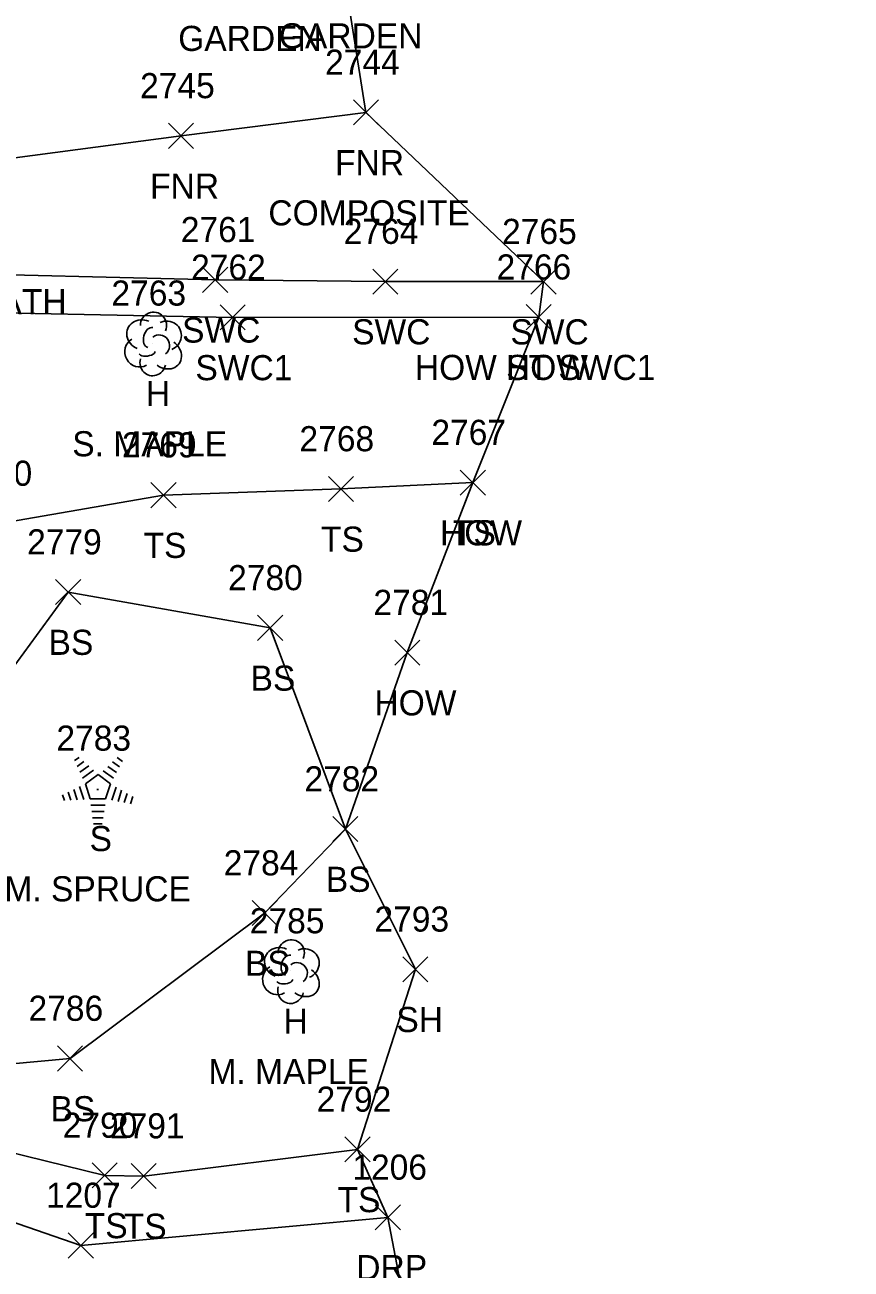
# Model space of a CAD drawing. Extents: x 1461855 to 1464118, y 556196 to 557441.
# Drawn here: x 1462432.1 to 1462498, y 556585 to 556684.1 of the extents above; entities that cross this region are included whole.
import ezdxf

# ---------------------------------------------------------------- set-up
doc = ezdxf.new("R2010")
doc.units = 0
for name, color, linetype in [('L_A', 7, 'Continuous'), ('L_C', 7, 'Continuous'), ('L_I', 7, 'Continuous'), ('L_TIC', 7, 'Continuous'), ('LBC', 7, 'Continuous'), ('LELB', 7, 'Continuous'), ('LFNC', 7, 'Continuous'), ('LSOGP', 7, 'Continuous'), ('LTC', 7, 'Continuous'), ('LTD', 7, 'Continuous'), ('R_A', 7, 'Continuous'), ('R_I', 7, 'Continuous'), ('R_TIC', 7, 'Continuous'), ('RDP', 7, 'Continuous'), ('RSW', 7, 'Continuous')]:
    doc.layers.add(name, color=color, linetype=linetype)

msp = doc.modelspace()

# ---------------------------------------------------------------- linework, layer by layer
at = {"layer": 'L_TIC'}
for points in [[(1462458.317, 556676.129), (1462460.317, 556678.129)], [(1462460.317, 556676.129), (1462458.317, 556678.129)], [(1462443.579, 556674.26), (1462445.579, 556676.26)], [(1462445.579, 556674.26), (1462443.579, 556676.26)], [(1462472.082, 556659.822), (1462474.082, 556661.822)], [(1462474.082, 556659.822), (1462472.082, 556661.822)], [(1462466.833, 556646.652), (1462468.833, 556648.652)], [(1462468.833, 556646.652), (1462466.833, 556648.652)], [(1462466.833, 556646.652), (1462468.833, 556648.652)], [(1462468.833, 556646.652), (1462466.833, 556648.652)], [(1462442.184, 556645.651), (1462444.184, 556647.651)], [(1462444.184, 556645.651), (1462442.184, 556647.651)], [(1462456.322, 556646.145), (1462458.322, 556648.145)], [(1462458.322, 556646.145), (1462456.322, 556648.145)], [(1462434.585, 556637.93), (1462436.585, 556639.93)], [(1462436.585, 556637.93), (1462434.585, 556639.93)], [(1462450.68, 556635.08), (1462452.68, 556637.08)], [(1462452.68, 556635.08), (1462450.68, 556637.08)], [(1462461.604, 556633.11), (1462463.604, 556635.11)], [(1462463.604, 556633.11), (1462461.604, 556635.11)], [(1462456.674, 556619.06), (1462458.674, 556621.06)], [(1462458.674, 556619.06), (1462456.674, 556621.06)], [(1462450.24, 556612.372), (1462452.24, 556614.372)], [(1462452.24, 556612.372), (1462450.24, 556614.372)], [(1462462.251, 556607.893), (1462464.251, 556609.893)], [(1462464.251, 556607.893), (1462462.251, 556609.893)], [(1462434.743, 556600.789), (1462436.743, 556602.789)], [(1462436.743, 556600.789), (1462434.743, 556602.789)], [(1462457.64, 556593.551), (1462459.64, 556595.551)], [(1462459.64, 556593.551), (1462457.64, 556595.551)], [(1462437.5, 556591.477), (1462439.5, 556593.477)], [(1462439.5, 556591.477), (1462437.5, 556593.477)], [(1462440.607, 556591.429), (1462442.607, 556593.429)], [(1462442.607, 556591.429), (1462440.607, 556593.429)]]:
    msp.add_lwpolyline(points, dxfattribs=at)
at = {"layer": 'LBC'}
msp.add_lwpolyline([(1462473.082, 556660.822), (1462467.833, 556647.652), (1462462.604, 556634.11)], dxfattribs=at)
at = {"layer": 'LELB'}
for points in [[(1462398.71, 556863.574), (1462402.391, 556852.24), (1462404.798, 556832.693), (1462410.819, 556809.539), (1462407.679, 556805.323), (1462406.455, 556784.092), (1462410.476, 556745.251), (1462412.025, 556715.66), (1462414.021, 556699.927), (1462415.956, 556675.834), (1462416.655, 556662.842), (1462419.224, 556640.169), (1462421.298, 556615.254), (1462423.719, 556596.606), (1462425.734, 556595.598), (1462438.5, 556592.477), (1462441.607, 556592.429), (1462458.64, 556594.551)], [(1462467.833, 556647.652), (1462457.322, 556647.145), (1462443.184, 556646.651), (1462430.121, 556644.395), (1462421.458, 556640.596)], [(1462423.571, 556615.497), (1462428.501, 556629.264), (1462435.585, 556638.93), (1462451.68, 556636.08), (1462457.674, 556620.06), (1462451.24, 556613.372), (1462435.743, 556601.789), (1462426.19, 556600.924)]]:
    msp.add_lwpolyline(points, dxfattribs=at)
at = {"layer": 'LFNC'}
msp.add_lwpolyline([(1462459.317, 556677.129), (1462444.579, 556675.26), (1462422.678, 556672.378), (1462423.303, 556665.036)], dxfattribs=at)
at = {"layer": 'LSOGP'}
msp.add_lwpolyline([(1462492.963, 556484.557), (1462497.969, 556513.067), (1462493.382, 556525.455), (1462494.578, 556544.983), (1462465.288, 556544.702), (1462464.985, 556558.784), (1462464.727, 556563.689), (1462463.774, 556573.431), (1462464.38, 556574.975), (1462463.349, 556577.214), (1462461.053, 556589.139), (1462458.64, 556594.551), (1462463.251, 556608.893), (1462457.674, 556620.06), (1462462.604, 556634.11), (1462467.833, 556647.652), (1462473.082, 556660.822), (1462473.463, 556663.653), (1462459.317, 556677.129), (1462457.706, 556687.223)], dxfattribs=at)
at = {"layer": 'LTC'}
for p, q in [((1462436.104, 556625.51), (1462436.458, 556625.767)), ((1462436.313, 556625.044), (1462436.842, 556625.429)), ((1462439.131, 556625.402), (1462439.68, 556625.003)), ((1462439.502, 556625.75), (1462439.921, 556625.446)), ((1462436.523, 556624.579), (1462437.227, 556625.09)), ((1462436.732, 556624.113), (1462437.611, 556624.751)), ((1462436.957, 556623.658), (1462437.969, 556624.392)), ((1462437.969, 556624.392), (1462438.966, 556623.667)), ((1462438.389, 556624.705), (1462439.198, 556624.117)), ((1462438.76, 556625.054), (1462439.439, 556624.56)), ((1462436.502, 556623.439), (1462436.833, 556622.42)), ((1462436.957, 556623.658), (1462437.344, 556622.465)), ((1462438.966, 556623.667), (1462438.574, 556622.465)), ((1462439.403, 556623.397), (1462439.065, 556622.357)), ((1462435.136, 556622.789), (1462435.288, 556622.321)), ((1462435.592, 556623.006), (1462435.803, 556622.354)), ((1462436.047, 556623.222), (1462436.318, 556622.387)), ((1462438.574, 556622.465), (1462437.344, 556622.465)), ((1462439.848, 556623.146), (1462439.56, 556622.262)), ((1462440.292, 556622.896), (1462440.055, 556622.167)), ((1462440.737, 556622.646), (1462440.55, 556622.072)), ((1462438.536, 556621.965), (1462437.392, 556621.965)), ((1462438.452, 556621.465), (1462437.464, 556621.465)), ((1462438.369, 556620.965), (1462437.537, 556620.965)), ((1462438.285, 556620.465), (1462437.61, 556620.465))]:
    msp.add_line(p, q, dxfattribs=at)
at = {"layer": 'LTD'}
for p, q in [((1462442.34, 556658.743), (1462442.34, 556658.743)), ((1462442.34, 556658.743), (1462442.34, 556658.743)), ((1462453.318, 556608.757), (1462453.318, 556608.757)), ((1462453.318, 556608.757), (1462453.318, 556608.757))]:
    msp.add_line(p, q, dxfattribs=at)
for centre in [(1462442.386, 556660.177), (1462453.364, 556610.191)]:
    msp.add_arc(centre, 1.047, 335.52715, 180.95627, dxfattribs=at)
for centre, major_axis, ratio, start_param, end_param in [((1462441.548, 556659.409), (1.21, -0.512), 0.895232, 1.570796, 4.712389), ((1462442.131, 556659.201), (-0.208, -0.792), 0.645439, 3.141593, 6.283185), ((1462443.381, 556659.326), (-1.141, -0.483), 0.949671, 1.570796, 4.712389), ((1462441.256, 556658.034), (0.584, -1.042), 0.959034, 3.141593, 6.283185), ((1462442.84, 556658.576), (-0.5, 0.667), 0.989748, 3.141593, 6.283185), ((1462441.881, 556657.993), (-0.625, -0.083), 0.423636, 0, 3.141593), ((1462443.34, 556657.909), (-1.09, 0.792), 0.841452, 1.570796, 4.712389), ((1462442.34, 556657.243), (0.265, 1.061), 0.942809, 1.570796, 4.712389), ((1462452.526, 556609.424), (1.21, -0.512), 0.895232, 1.570796, 4.712389), ((1462454.359, 556609.341), (-1.141, -0.483), 0.949671, 1.570796, 4.712389), ((1462453.109, 556609.216), (-0.208, -0.792), 0.645439, 3.141593, 6.283185), ((1462453.818, 556608.591), (-0.5, 0.667), 0.989748, 3.141593, 6.283185), ((1462452.234, 556608.049), (0.584, -1.042), 0.959034, 3.141593, 6.283185), ((1462454.318, 556607.924), (-1.09, 0.792), 0.841452, 1.570796, 4.712389), ((1462452.859, 556608.007), (-0.625, -0.083), 0.423636, 0, 3.141593), ((1462453.318, 556607.257), (0.265, 1.061), 0.942809, 1.570796, 4.712389)]:
    msp.add_ellipse(centre, major_axis=major_axis, ratio=ratio, start_param=start_param, end_param=end_param, dxfattribs=at)
at = {"layer": 'R_TIC'}
for points in [[(1462446.302, 556662.799), (1462448.302, 556664.799)], [(1462448.302, 556662.799), (1462446.302, 556664.799)], [(1462459.851, 556662.657), (1462461.851, 556664.657)], [(1462461.851, 556662.657), (1462459.851, 556664.657)], [(1462472.463, 556662.653), (1462474.463, 556664.653)], [(1462474.463, 556662.653), (1462472.463, 556664.653)], [(1462447.689, 556659.802), (1462449.689, 556661.802)], [(1462449.689, 556659.802), (1462447.689, 556661.802)], [(1462472.082, 556659.822), (1462474.082, 556661.822)], [(1462474.082, 556659.822), (1462472.082, 556661.822)], [(1462460.053, 556588.139), (1462462.053, 556590.139)], [(1462462.053, 556588.139), (1462460.053, 556590.139)], [(1462435.599, 556585.899), (1462437.599, 556587.899)], [(1462437.599, 556585.899), (1462435.599, 556587.899)]]:
    msp.add_lwpolyline(points, dxfattribs=at)
at = {"layer": 'RDP'}
msp.add_lwpolyline([(1462461.053, 556589.139), (1462436.599, 556586.899), (1462425.208, 556590.833), (1462420.115, 556594.818)], dxfattribs=at)
at = {"layer": 'RSW'}
for points in [[(1462417.807, 556664.464), (1462423.409, 556664.372), (1462447.302, 556663.799), (1462460.851, 556663.657), (1462473.463, 556663.653)], [(1462417.807, 556664.464), (1462418.428, 556659.28), (1462422.306, 556659.233), (1462422.398, 556661.333), (1462448.689, 556660.802), (1462473.082, 556660.822)]]:
    msp.add_lwpolyline(points, dxfattribs=at)

# ---------------------------------------------------------------- texts
at = {"layer": 'L_A'}
for s, p in [('GARDEN', (1462444.357, 556682.022)), ('GARDEN', (1462452.375, 556682.223)), ('FNR', (1462456.852, 556672.129)), ('FNR', (1462442.114, 556670.26)), ('HOW', (1462470.468, 556655.822)), ('H', (1462441.773, 556653.743)), ('HOW', (1462465.219, 556642.652)), ('TS', (1462466.243, 556642.652)), ('TS', (1462441.593, 556641.651)), ('TS', (1462455.731, 556642.145)), ('BS', (1462434.026, 556633.93)), ('BS', (1462450.121, 556631.08)), ('HOW', (1462459.99, 556629.11)), ('S', (1462437.294, 556618.302)), ('BS', (1462456.115, 556615.06)), ('BS', (1462449.681, 556608.372)), ('H', (1462452.751, 556603.757)), ('SH', (1462461.739, 556603.893)), ('BS', (1462434.184, 556596.789)), ('TS', (1462457.049, 556589.551)), ('TS', (1462436.91, 556587.477)), ('TS', (1462440.017, 556587.429))]:
    msp.add_text(s, height=2, dxfattribs=at).set_placement(p)
at = {"layer": 'L_C'}
for s, p in [('COMPOSITE', (1462451.537, 556668.129)), ('BRIDLE WREATH', (1462413.471, 556661.058)), ('S. MAPLE', (1462435.914, 556649.743)), ('M. SPRUCE', (1462430.507, 556614.302)), ('M. MAPLE', (1462446.766, 556599.757))]:
    msp.add_text(s, height=2, dxfattribs=at).set_placement(p)
at = {"layer": 'L_I'}
for s, p in [('2744', (1462456.057, 556680.129)), ('2745', (1462441.319, 556678.26)), ('2766', (1462469.72, 556663.822)), ('2763', (1462439.033, 556661.743)), ('2768', (1462454.015, 556650.145)), ('2767', (1462464.526, 556650.652)), ('2767', (1462464.526, 556650.652)), ('2769', (1462439.869, 556649.651)), ('2770', (1462426.775, 556647.395)), ('2779', (1462432.317, 556641.93)), ('2780', (1462448.333, 556639.08)), ('2781', (1462459.911, 556637.11)), ('2783', (1462434.649, 556626.302)), ('2782', (1462454.414, 556623.06)), ('2784', (1462447.981, 556616.372)), ('2785', (1462450.058, 556611.757)), ('2793', (1462459.991, 556611.893)), ('2786', (1462432.428, 556604.789)), ('2792', (1462455.38, 556597.551)), ('2790', (1462435.154, 556595.477)), ('2791', (1462438.914, 556595.429))]:
    msp.add_text(s, height=2, dxfattribs=at).set_placement(p)
at = {"layer": 'LTC'}
msp.add_text('.', height=1.037, rotation=270, dxfattribs=at).set_placement((1462437.851, 556623.406))
at = {"layer": 'R_A'}
for s, p in [('SWC', (1462444.664, 556658.799)), ('SWC', (1462458.213, 556658.657)), ('SWC', (1462470.825, 556658.653)), ('SWC1', (1462445.728, 556655.802)), ('HOW ST SWC1', (1462463.208, 556655.822)), ('DRP', (1462458.542, 556584.139))]:
    msp.add_text(s, height=2, dxfattribs=at).set_placement(p)
at = {"layer": 'R_I'}
for s, p in [('2761', (1462444.561, 556666.799)), ('2764', (1462457.543, 556666.657)), ('2765', (1462470.156, 556666.653)), ('2762', (1462445.382, 556663.802)), ('2766', (1462469.72, 556663.822)), ('1206', (1462458.227, 556592.139)), ('1207', (1462433.828, 556589.899))]:
    msp.add_text(s, height=2, dxfattribs=at).set_placement(p)

doc.saveas('drawing.dxf')
